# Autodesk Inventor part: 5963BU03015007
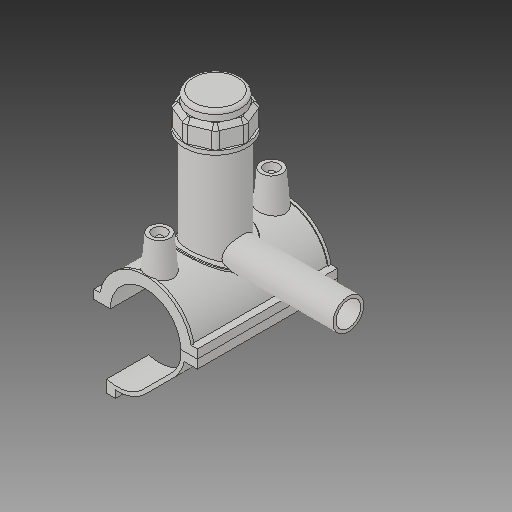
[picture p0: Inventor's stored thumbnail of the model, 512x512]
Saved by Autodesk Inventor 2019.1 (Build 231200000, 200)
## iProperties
Created: 2017-07
Part Number: 5963BU03015007
Material: Generic
Description: PLASSON TAPPING SADDLE 1 1/2''IPS x 1 3/4''CTS
Document SubType Name: Modeling
Designer: KIM
Mass: 1712.7 g
Surface Area: 2671.49 cm^2
Volume: 1712.7 cm^3
Density: 1 g/cm^3
Appearance: Default
Author: KIM
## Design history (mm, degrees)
derived "5963B.ipt"
feature "Solid1::5963B.ipt"
feature "Solid2::5963B.ipt"
feature "Solid4::5963B.ipt"
feature "Solid5::5963B.ipt"
tag "TaggingFeature1"
body "Solid1"
body "Solid2"
other parameters: "d_" = 50.1, "B_" = 74.168, "L_" = 100.076, "d_t" = 6, "H_2" = 98.044, "H_1" = 6.858, "d_1" = 22.1, "H_" = 94.996, "d1" = 65.13, "d148" = 0.7515, "d160" = 0.7515, "d169" = 3.2805, "d192" = 6.1236, "d0" = 50.1, "d2" = 74.168, "d3" = 12.525, "d4" = 100.076, "d5" = 0, "d6" = 0.1, "d8" = 0, "d19" = 6, "d20" = 6, "d21" = 60.0456, "d23" = 0, "d24" = 30.0228, "d26" = 0, "d29" = 3, "d30" = 16.7, "d31" = 6, "d32" = 0, "d33" = 0, "d34" = 0.6, "d40" = 33.8676, "d41" = 45.09, "d43" = 0, "d45" = 0, "d47" = 92.6106, "d70" = 15, "d72" = 0, "d73" = 6, "d75" = 5, "d76" = 0, "d77" = 2.505, "d78" = 55.05, "d79" = 15, "d80" = 40.0304, "d82" = 5 deg, "d84" = 4, "d85" = 14, "d86" = 0, "d87" = 3, "d88" = 0, "d89" = 1, "d90" = 1, "d91" = 80.0608, "d92" = 0, "d93" = 0.5, "d94" = 26.36842, "d96" = 66.4326, "d97" = 2.00152, "d98" = 0, "d102" = 0.501, "d120" = 140 deg, "d121" = 24.228, "d122" = 20 deg, "d123" = 130.26, "d124" = 39.078, "d126" = 0, "d143" = 51.603, "d145" = 11.56154, "d149" = 0.7515, "d150" = 12.71769, "d153" = 100.076, "d154" = 0, "d156" = 32.565, "d157" = 160 deg, "d159" = 3.006, "d161" = 0.7515, "d162" = 60.0456, "d163" = 0, "d164" = 25.05, "d167" = 5.01, "d168" = 31.77073, "d170" = 3.2805, "d172" = 0, "d173" = 1, "d175" = 25.05, "d176" = 20 deg, "d177" = 3.507, "d178" = 15.03, "d180" = 0, "d183" = 6.012, "d184" = 2.8056, "d185" = 32.5247, "d186" = 32.5247, "d187" = 32.565, "d188" = 4.509, "d189" = 3.507, "d190" = 0, "d191" = 48.8475, "d193" = 6.1236, "d194" = 3.50266, "d195" = 90 deg, "d197" = 0, "d199" = 0, "d200" = 7.515, "d202" = 0, "d203" = 98.044, "d204" = 42.8355, "d205" = 31.563, "d206" = 38.3265, "d207" = 73.533, "d208" = 76.47432, "d209" = 91.18092, "d210" = 38.7774, "d211" = 45.09, "d212" = 36.072, "d213" = -3.7728, "d216" = 0, "d217" = 5.01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
